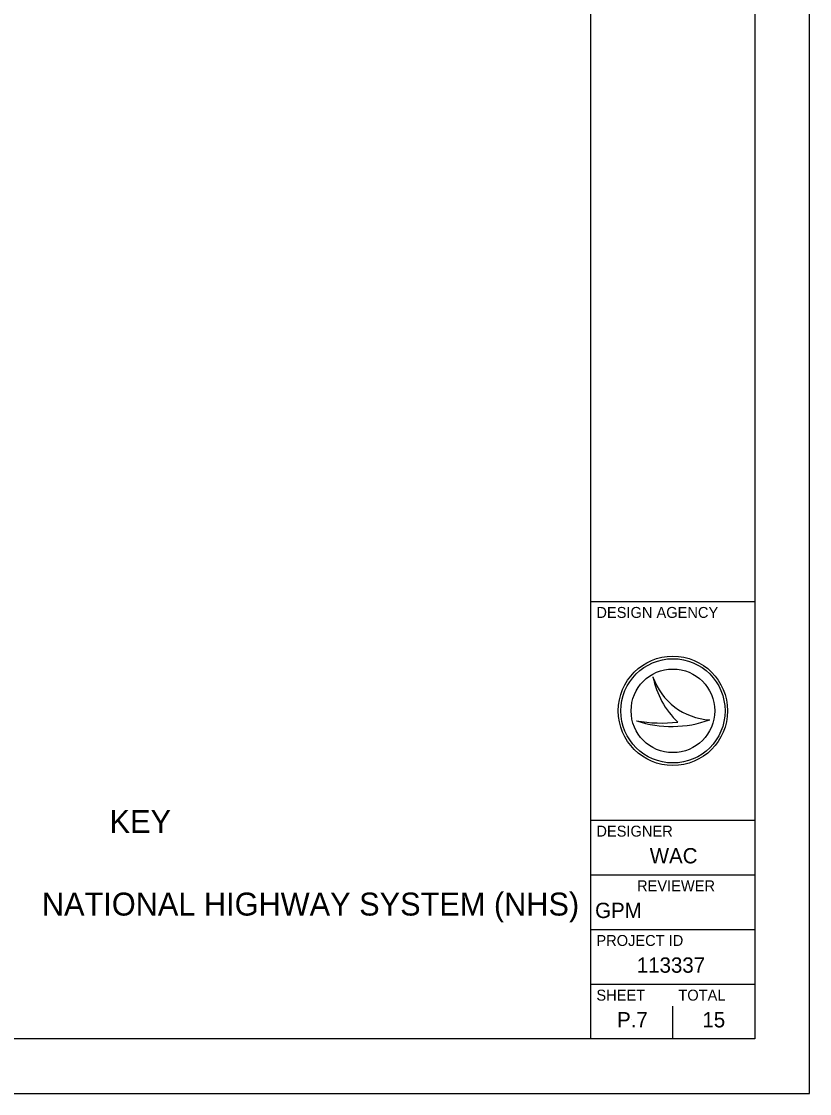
# Model space of a CAD drawing. Extents: x 2015843 to 2287843, y 623733 to 799733.
# Drawn here: x 2230169 to 2287843, y 623733 to 702171 of the extents above; entities that cross this region are included whole.
import ezdxf

# ---------------------------------------------------------------- set-up
doc = ezdxf.new("R2010")
doc.units = 0
for name, color, linetype in [('SH_Border', 7, 'Continuous'), ('SH_Cut_Line', 7, 'Continuous'), ('SH_Data', 7, 'Continuous'), ('UT_P_Electric', 7, 'Continuous')]:
    doc.layers.add(name, color=color, linetype=linetype)

msp = doc.modelspace()

# ---------------------------------------------------------------- linework, layer by layer
at = {"layer": 'SH_Border'}
for p, q in [((2271843, 627733), (2271843, 795733)), ((2271843, 659733), (2283843, 659733)), ((2271843, 643733), (2283843, 643733)), ((2271843, 639733), (2283843, 639733)), ((2271843, 635733), (2283843, 635733)), ((2271843, 631733), (2283843, 631733))]:
    msp.add_line(p, q, dxfattribs=at)
msp.add_lwpolyline([(2027843, 795733), (2283843, 795733), (2283843, 627733), (2027843, 627733)], close=True, dxfattribs=at)
at = {"layer": 'SH_Cut_Line'}
msp.add_lwpolyline([(2015843, 623733), (2287843, 623733), (2287843, 799733), (2015843, 799733)], close=True, dxfattribs=at)
at = {"layer": 'SH_Data'}
for p, q in [((2276383, 654210), (2276383, 654210)), ((2277843, 651733), (2277843, 651733)), ((2280541, 651081), (2280541, 651081)), ((2275180, 651009), (2275180, 651009)), ((2277843, 627733), (2277843, 630133)), ((2274843, 629133), (2274843, 629133))]:
    msp.add_line(p, q, dxfattribs=at)
for radius in [4000, 3814, 3814, 3058]:
    msp.add_circle((2277843, 651733), radius, dxfattribs=at)
for centre, radius, start, end in [((2280771, 655714), 4639, 198.92567, 198.93195), ((2282616, 655494), 6365, 191.63793, 191.64215), ((2280771, 655714), 4639, 198.93195, 267.16574), ((2282616, 655494), 6365, 191.64215, 226.09467), ((2277758, 658693), 8105, 251.45764, 290.08324), ((2277027, 660968), 10128, 259.49639, 259.49952), ((2277758, 658693), 8105, 251.45274, 251.45764), ((2277027, 660968), 10128, 259.49952, 276.66723)]:
    msp.add_arc(centre, radius, start, end, dxfattribs=at)

# ---------------------------------------------------------------- texts
for s, height, p in [('DESIGN AGENCY', 800, (2272243, 658533)), ('DESIGNER', 800, (2272243, 642533)), ('WAC', 1120, (2276147, 640573)), ('REVIEWER', 800, (2275218, 638533)), ('GPM', 1120, (2272150, 636573)), ('PROJECT ID', 800, (2272243, 634533)), ('113337', 1120, (2275202, 632573)), ('SHEET', 800, (2272243, 630533)), ('TOTAL', 800, (2278243, 630533)), ('P.7', 1120, (2273758, 628573)), ('15', 1120, (2280001, 628573))]:
    msp.add_text(s, height=height, dxfattribs=at).set_placement(p)
at = {"layer": 'UT_P_Electric'}
for s, p in [('KEY', (2236619, 642801)), ('NATIONAL HIGHWAY SYSTEM (NHS)', (2231666, 636755))]:
    msp.add_text(s, height=1680, dxfattribs=at).set_placement(p)

doc.saveas('drawing.dxf')
